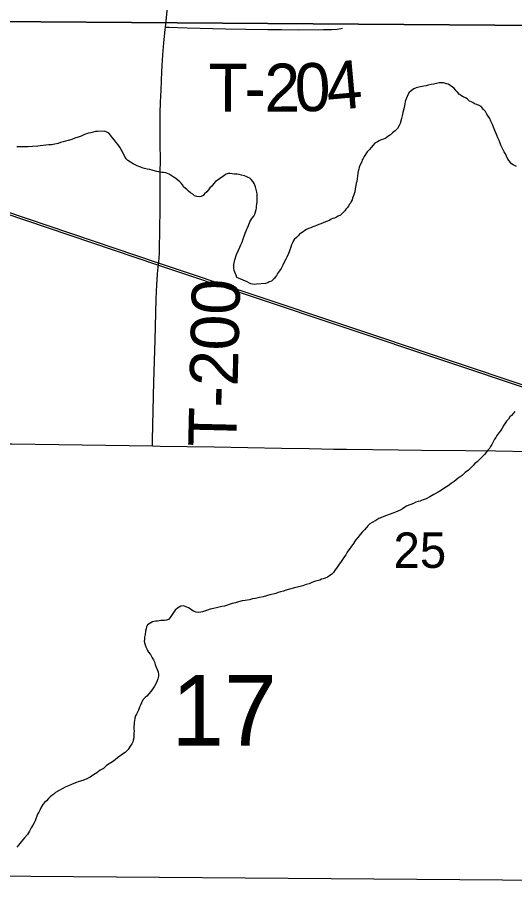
# Model space of a CAD drawing. Extents: x 2.4 to 73.1, y 4.5 to 25.6.
# Drawn here: x 33.042 to 33.336, y 22.115 to 22.627 of the extents above; entities that cross this region are included whole.
import ezdxf

# ---------------------------------------------------------------- set-up
doc = ezdxf.new("R2010")
doc.units = 0
for name, color, linetype in [('GM_X_County_Road', 7, 'Continuous'), ('GM_X_Minor_River', 7, 'Continuous'), ('GM_X_Rail_Line', 7, 'Continuous'), ('GM_X_Section', 7, 'Continuous'), ('GM_X_Section_Text', 7, 'Continuous'), ('GM_X_Township_Road', 7, 'Continuous'), ('GM_X_Township_Road_Text', 7, 'Continuous')]:
    doc.layers.add(name, color=color, linetype=linetype)

msp = doc.modelspace()

# ---------------------------------------------------------------- linework, layer by layer
at = {"layer": 'GM_X_County_Road'}
for points in [[(33.02645, 22.37476), (33.03888, 22.37466), (33.1082, 22.37368), (33.12199, 22.37343)], [(33.12199, 22.37343), (33.12654, 22.37335), (33.15855, 22.37294), (33.19834, 22.37219), (33.2145, 22.37194), (33.2291, 22.37161), (33.23656, 22.37157), (33.26734, 22.37111), (33.28101, 22.37095), (33.30712, 22.37067), (33.32484, 22.37046), (33.34473, 22.3702), (33.35934, 22.36986), (33.37363, 22.3697), (33.38233, 22.36961), (33.39788, 22.36951), (33.43642, 22.36906), (33.46004, 22.36895), (33.47186, 22.36883), (33.49797, 22.36822), (33.51599, 22.36802), (33.51997, 22.36798), (33.53391, 22.3678)]]:
    msp.add_lwpolyline(points, dxfattribs=at)
at = {"layer": 'GM_X_Minor_River'}
for points in [[(33.3371, 22.53863), (33.33522, 22.53963), (33.3341, 22.54023), (33.33281, 22.54197), (33.33207, 22.54294), (33.33117, 22.54467), (33.33063, 22.54601), (33.3299, 22.54717), (33.329, 22.5489), (33.32845, 22.55006), (33.32791, 22.55121), (33.32737, 22.55236), (33.32684, 22.5539), (33.32612, 22.55562), (33.3254, 22.55716), (33.32487, 22.5585), (33.32433, 22.55985), (33.32362, 22.56176), (33.3229, 22.56349), (33.322, 22.56541), (33.32128, 22.56695), (33.32036, 22.5683), (33.31963, 22.56946), (33.31872, 22.571), (33.31762, 22.57236), (33.31633, 22.5741), (33.31502, 22.5747), (33.3137, 22.57531), (33.31238, 22.57572), (33.31126, 22.57632), (33.30938, 22.57713), (33.30789, 22.57849), (33.30696, 22.57909), (33.30564, 22.57969), (33.30452, 22.58029), (33.3034, 22.58108), (33.30229, 22.58243), (33.30118, 22.5836), (33.30027, 22.58495), (33.29877, 22.58594), (33.29765, 22.58673), (33.29672, 22.58732), (33.29577, 22.58754), (33.29407, 22.58796), (33.29275, 22.58799), (33.29142, 22.58803), (33.28989, 22.58768), (33.28836, 22.58734), (33.28664, 22.58701), (33.28493, 22.58667), (33.28378, 22.58632), (33.28244, 22.58598), (33.2813, 22.58581), (33.28034, 22.58565), (33.27939, 22.58548), (33.27786, 22.58514), (33.27651, 22.58442), (33.27478, 22.58332), (33.27341, 22.58203), (33.27241, 22.57996), (33.272, 22.57865), (33.27139, 22.57695), (33.27116, 22.57544), (33.27073, 22.57355), (33.2699, 22.57053), (33.26946, 22.56845), (33.26924, 22.56694), (33.2684, 22.56392), (33.2678, 22.5628), (33.26681, 22.56111), (33.26545, 22.55963), (33.2639, 22.55853), (33.26273, 22.55723), (33.26099, 22.55632), (33.25983, 22.5554), (33.25848, 22.55468), (33.25715, 22.55433), (33.25599, 22.55379), (33.25503, 22.55325), (33.25349, 22.55234), (33.25213, 22.55104), (33.25134, 22.55011), (33.24997, 22.54844), (33.2488, 22.54733), (33.24702, 22.54452), (33.24643, 22.5434), (33.24583, 22.54247), (33.24562, 22.54133), (33.24461, 22.53927), (33.24421, 22.53814), (33.24399, 22.53701), (33.24358, 22.53588), (33.24335, 22.53436), (33.24313, 22.53304)], [(33.18342, 22.51499), (33.18365, 22.51651), (33.18386, 22.51745), (33.1839, 22.51897), (33.18394, 22.52068), (33.18379, 22.5222), (33.18363, 22.52334), (33.18295, 22.52659), (33.1824, 22.52755), (33.18205, 22.52851), (33.1815, 22.52947), (33.1804, 22.53083), (33.17947, 22.53162), (33.17853, 22.53202), (33.1774, 22.53262), (33.17646, 22.53302), (33.17457, 22.53345), (33.17325, 22.53386), (33.17193, 22.53409), (33.17041, 22.53412), (33.16908, 22.53416), (33.16776, 22.53438), (33.16662, 22.53441), (33.16509, 22.53388), (33.16392, 22.53296), (33.16238, 22.53186), (33.16083, 22.53076), (33.15928, 22.52966), (33.15811, 22.52836), (33.15713, 22.52705), (33.15596, 22.52594), (33.15517, 22.52482), (33.15419, 22.52352), (33.15283, 22.52241), (33.15186, 22.52149), (33.15071, 22.52095), (33.14956, 22.5206), (33.14824, 22.52082), (33.14692, 22.52124), (33.1458, 22.52221), (33.14449, 22.52301), (33.14338, 22.52398), (33.14245, 22.52477), (33.1404, 22.52653), (33.13986, 22.52749), (33.13894, 22.52865), (33.1382, 22.52962), (33.1369, 22.53061), (33.13578, 22.53158), (33.13428, 22.53257), (33.13298, 22.53336), (33.13185, 22.53396), (33.13091, 22.53436), (33.12997, 22.53477), (33.12846, 22.535), (33.12751, 22.53502), (33.12657, 22.53524), (33.12449, 22.53567), (33.12241, 22.53629), (33.12052, 22.53672), (33.11882, 22.53695), (33.11731, 22.53737), (33.11599, 22.53778), (33.11505, 22.53819), (33.11392, 22.53859), (33.11298, 22.539), (33.11186, 22.5396), (33.11054, 22.5402), (33.10905, 22.54119), (33.10737, 22.54218), (33.10644, 22.54315), (33.10589, 22.54411), (33.10517, 22.54546), (33.10408, 22.54758), (33.10354, 22.54873), (33.10262, 22.55008), (33.10171, 22.55144), (33.10079, 22.5526), (33.0995, 22.55415), (33.09839, 22.55551), (33.09729, 22.55706), (33.09618, 22.55822), (33.09468, 22.55902), (33.09355, 22.55943), (33.08956, 22.55934), (33.08842, 22.55918), (33.08689, 22.55884), (33.08555, 22.55849), (33.08422, 22.55834), (33.08287, 22.5578), (33.08134, 22.55727), (33.0798, 22.55655), (33.07808, 22.55583), (33.07616, 22.55531), (33.07444, 22.5546), (33.07214, 22.5539), (33.07061, 22.55355), (33.06927, 22.55321), (33.06774, 22.55268), (33.06621, 22.55215), (33.0643, 22.55181)], [(33.0643, 22.55181), (33.06239, 22.55148), (33.06068, 22.55134), (33.05897, 22.55119), (33.05744, 22.55104), (33.05573, 22.55089), (33.0542, 22.55055), (33.05116, 22.55044), (33.0485, 22.55013), (33.04603, 22.55019), (33.04394, 22.55024), (33.04185, 22.55029)], [(33.24313, 22.53304), (33.2429, 22.53134), (33.24267, 22.52982), (33.24245, 22.52869), (33.24223, 22.52737), (33.2418, 22.52548), (33.24156, 22.52358), (33.24095, 22.52189), (33.24055, 22.52095), (33.24014, 22.51982), (33.23993, 22.51888), (33.23933, 22.51794), (33.23893, 22.517), (33.23833, 22.51607), (33.23774, 22.51514), (33.23696, 22.51421), (33.23618, 22.51328), (33.23558, 22.51234), (33.23305, 22.50975), (33.23171, 22.50921), (33.23074, 22.50867), (33.22959, 22.50813), (33.22863, 22.50777), (33.22767, 22.50741), (33.22671, 22.50687), (33.22537, 22.50633), (33.22421, 22.50579), (33.22287, 22.50526), (33.22153, 22.50472), (33.22038, 22.50437), (33.21884, 22.50365), (33.21788, 22.50329), (33.21673, 22.50294), (33.21558, 22.5024), (33.21424, 22.50187), (33.21309, 22.50133), (33.21212, 22.50078), (33.21097, 22.50005), (33.21, 22.49932), (33.20884, 22.49859), (33.20806, 22.49766), (33.20708, 22.49654), (33.20572, 22.49544), (33.20513, 22.4945), (33.20473, 22.49356), (33.20412, 22.49225), (33.20371, 22.49093), (33.2031, 22.48943), (33.20269, 22.48811), (33.20229, 22.48717), (33.20148, 22.4851), (33.20087, 22.48379), (33.19988, 22.4821), (33.19907, 22.48022), (33.19808, 22.47835), (33.19709, 22.47686), (33.19591, 22.47537), (33.19532, 22.47424), (33.19472, 22.47331), (33.19394, 22.47238), (33.19238, 22.4709), (33.19104, 22.47036), (33.19008, 22.46982), (33.18874, 22.46947), (33.18341, 22.46904), (33.18208, 22.46888), (33.18113, 22.46909), (33.18019, 22.46931), (33.17925, 22.46971), (33.17794, 22.4705), (33.17568, 22.47132), (33.17417, 22.47193), (33.17286, 22.47253), (33.17192, 22.47294), (33.17139, 22.47428), (33.17103, 22.47524), (33.17067, 22.4762), (33.17032, 22.47715), (33.16998, 22.47868), (33.17003, 22.48077), (33.17066, 22.48341), (33.17169, 22.48661), (33.1729, 22.48924), (33.1737, 22.49093), (33.1743, 22.49225), (33.17491, 22.49394), (33.17553, 22.49582), (33.17614, 22.49733), (33.17676, 22.49921), (33.17736, 22.50052), (33.17776, 22.50146), (33.17817, 22.5024), (33.17877, 22.50372), (33.17958, 22.50579), (33.18077, 22.50784), (33.18195, 22.50933), (33.18255, 22.51046), (33.18296, 22.51178), (33.18318, 22.5131), (33.18339, 22.51404), (33.18342, 22.51499)], [(33.33613, 22.39376), (33.33516, 22.39265), (33.33418, 22.39153), (33.3332, 22.39061), (33.33241, 22.3893), (33.33124, 22.388), (33.33045, 22.38688), (33.32966, 22.38576), (33.32867, 22.38388), (33.32768, 22.38239), (33.3267, 22.38127), (33.32552, 22.3796), (33.32492, 22.37847), (33.32414, 22.37735), (33.32334, 22.37585), (33.32254, 22.37435), (33.32175, 22.37305), (33.32115, 22.37192), (33.32018, 22.371), (33.31959, 22.37006), (33.31821, 22.36839), (33.31393, 22.36413), (33.31257, 22.36302), (33.3114, 22.36172), (33.31004, 22.36043), (33.30868, 22.35913), (33.30674, 22.35766), (33.30499, 22.356), (33.30267, 22.35435), (33.30034, 22.35251)], [(33.30034, 22.35251), (33.29841, 22.35123), (33.29667, 22.34994), (33.29474, 22.34866), (33.29281, 22.34738), (33.29088, 22.3461), (33.28818, 22.34465), (33.28587, 22.34338), (33.28375, 22.3421), (33.28145, 22.3414), (33.28011, 22.34087), (33.27896, 22.34052), (33.27762, 22.34017), (33.27628, 22.33944), (33.27474, 22.33891), (33.2734, 22.33838), (33.27206, 22.33784), (33.27109, 22.3373), (33.26974, 22.33619), (33.26839, 22.33547), (33.26705, 22.33493), (33.2657, 22.3344), (33.26455, 22.33385), (33.26187, 22.33297), (33.25976, 22.33208), (33.25727, 22.33119), (33.25573, 22.33047), (33.25399, 22.32938), (33.25188, 22.32829), (33.25052, 22.32737), (33.24955, 22.32645), (33.24838, 22.32515), (33.24721, 22.32385), (33.24584, 22.32255), (33.24467, 22.32106), (33.2433, 22.31939), (33.24192, 22.31772), (33.24074, 22.31585), (33.237, 22.31063), (33.2362, 22.30913), (33.23542, 22.30801), (33.23463, 22.30689), (33.23384, 22.30577), (33.23305, 22.30465), (33.23226, 22.30353), (33.23148, 22.30241), (33.23069, 22.30129), (33.2299, 22.30017), (33.22891, 22.29868), (33.22794, 22.29775), (33.22658, 22.29665), (33.22543, 22.29591), (33.22408, 22.29538), (33.22293, 22.29484), (33.22198, 22.29467), (33.22082, 22.29413), (33.2193, 22.29379), (33.21834, 22.29344), (33.21719, 22.29308), (33.21585, 22.29255), (33.2145, 22.29201), (33.21278, 22.29149), (33.21086, 22.29078), (33.20857, 22.29027), (33.20589, 22.28957), (33.20303, 22.28889), (33.20092, 22.28818), (33.19939, 22.28765), (33.19767, 22.28731), (33.19633, 22.28678), (33.19499, 22.28624), (33.19327, 22.2859), (33.19135, 22.28538), (33.18944, 22.28486), (33.18734, 22.28435), (33.18524, 22.28383), (33.18295, 22.28332), (33.18104, 22.28299), (33.17932, 22.28246), (33.17684, 22.28214), (33.17493, 22.28181), (33.17283, 22.28129), (33.17111, 22.28077), (33.16919, 22.28025), (33.1646, 22.27884), (33.16307, 22.2785), (33.16136, 22.27817), (33.15983, 22.27783), (33.1581, 22.2773), (33.15601, 22.27697), (33.15448, 22.27644), (33.15275, 22.27573), (33.1516, 22.27538), (33.15065, 22.27521), (33.14912, 22.27506), (33.1478, 22.27528), (33.14629, 22.27589), (33.14535, 22.27629), (33.14423, 22.27708), (33.1433, 22.27767), (33.14236, 22.27808)], [(33.14236, 22.27808), (33.14048, 22.27889), (33.13877, 22.27874), (33.13781, 22.27819), (33.13684, 22.27765), (33.13548, 22.27635), (33.1345, 22.27505), (33.13371, 22.27374), (33.13252, 22.27206), (33.13155, 22.27095), (33.1302, 22.27041), (33.12906, 22.27025), (33.12792, 22.27028), (33.12697, 22.2703), (33.12602, 22.27014), (33.12506, 22.26997), (33.12392, 22.26981), (33.12297, 22.26964), (33.12201, 22.26948), (33.12009, 22.26839), (33.11912, 22.26765), (33.11852, 22.26653), (33.1183, 22.26539), (33.11789, 22.26388), (33.11765, 22.26199), (33.11723, 22.26048), (33.11719, 22.25897), (33.11717, 22.25802), (33.11733, 22.25706), (33.11769, 22.25591), (33.11804, 22.25477), (33.11858, 22.25361), (33.11912, 22.25246), (33.11966, 22.2515), (33.12077, 22.25014), (33.12186, 22.24821), (33.12259, 22.24705), (33.12313, 22.2459), (33.12367, 22.24437), (33.12419, 22.24265), (33.12491, 22.24092), (33.12545, 22.23976), (33.12561, 22.23862), (33.12558, 22.23729), (33.12516, 22.23578), (33.12475, 22.23465), (33.12415, 22.23334), (33.12315, 22.23147), (33.12197, 22.2296), (33.12098, 22.22829), (33.11981, 22.22699), (33.11864, 22.2255), (33.11767, 22.22477), (33.11631, 22.22347), (33.1149, 22.22028), (33.11429, 22.21897), (33.11368, 22.21727), (33.11308, 22.21615), (33.11249, 22.21502), (33.11189, 22.2139), (33.11166, 22.21258), (33.11144, 22.21106), (33.11122, 22.21012), (33.11119, 22.20898), (33.11097, 22.20766), (33.11094, 22.20652), (33.11109, 22.20481), (33.11106, 22.20348), (33.11103, 22.20234), (33.111, 22.20101), (33.11058, 22.1995), (33.11037, 22.19856), (33.10977, 22.19743), (33.10878, 22.19594), (33.10759, 22.19407), (33.10584, 22.19221), (33.10487, 22.19167), (33.10352, 22.19075), (33.10139, 22.1891), (33.10003, 22.18799), (33.09829, 22.18671), (33.09637, 22.18562), (33.09482, 22.18452), (33.09307, 22.18285), (33.09114, 22.18176), (33.08921, 22.18029), (33.08708, 22.17902), (33.08515, 22.17774), (33.08323, 22.17664), (33.08093, 22.17575), (33.07863, 22.17505), (33.07652, 22.17434), (33.07422, 22.17345), (33.0723, 22.17255), (33.07038, 22.17184), (33.06479, 22.16856), (33.06363, 22.16764), (33.06247, 22.16691), (33.0615, 22.16599), (33.06053, 22.16506), (33.05935, 22.16376)], [(33.05935, 22.16376), (33.05819, 22.16265), (33.05721, 22.16154), (33.05622, 22.16005), (33.05562, 22.15854), (33.05482, 22.15704), (33.05403, 22.15573), (33.05362, 22.1546), (33.05301, 22.1531), (33.0526, 22.15197), (33.052, 22.15066), (33.05121, 22.14935), (33.05041, 22.14766), (33.04941, 22.14578), (33.04822, 22.14373), (33.04646, 22.14187), (33.04548, 22.14057), (33.04431, 22.13946), (33.04275, 22.1376), (33.04176, 22.13629)]]:
    msp.add_lwpolyline(points, dxfattribs=at)
at = {"layer": 'GM_X_Rail_Line'}
for points in [[(32.73645, 22.61193), (33.12493, 22.48054), (33.46002, 22.36848), (33.53437, 22.34358), (33.5691, 22.33375), (33.59988, 22.32785), (33.62445, 22.32326), (33.65262, 22.31965), (33.6821, 22.31769), (34.03881, 22.31179), (34.37193, 22.30622), (34.42761, 22.30589), (34.46888, 22.30458), (34.50754, 22.3072), (34.56158, 22.31015), (34.62578, 22.31539), (34.67295, 22.31965), (34.92476, 22.34017)], [(32.73685, 22.61311), (33.12533, 22.48172), (33.46041, 22.36966), (33.53474, 22.34476), (33.56938, 22.33496), (33.60012, 22.32907), (33.62465, 22.32449), (33.65274, 22.32089), (33.68215, 22.31893), (34.03883, 22.31303), (34.37194, 22.30746), (34.42764, 22.30713), (34.46886, 22.30582), (34.50746, 22.30844), (34.5615, 22.31139), (34.62568, 22.31663), (34.67285, 22.32089), (34.92723, 22.34151)]]:
    msp.add_lwpolyline(points, dxfattribs=at)
at = {"layer": 'GM_X_Section'}
for points in [[(33.54562, 23.11902), (33.5389, 22.62058), (33.02904, 22.62432), (33.03536, 23.12164)], [(33.5389, 22.62058), (33.53887, 22.61906), (33.53166, 22.11533), (33.02446, 22.1192), (33.02904, 22.62432)]]:
    msp.add_lwpolyline(points, close=True, dxfattribs=at)
at = {"layer": 'GM_X_Township_Road'}
for points in [[(33.12965, 22.62102), (33.13029, 22.6265), (33.13135, 22.63671), (33.133, 22.65217), (33.13505, 22.67071), (33.13653, 22.68368), (33.13807, 22.69727), (33.13927, 22.70872), (33.1394, 22.71012), (33.1395, 22.71133)], [(33.12199, 22.37343), (33.12207, 22.37708), (33.12273, 22.41139), (33.12354, 22.43594), (33.12427, 22.46019), (33.12466, 22.46888), (33.12479, 22.47136), (33.12501, 22.47509), (33.12533, 22.47911), (33.12568, 22.48219), (33.12591, 22.48466), (33.12606, 22.48745), (33.12619, 22.49117), (33.12638, 22.49987), (33.1265, 22.51511), (33.12664, 22.53438), (33.12665, 22.54308), (33.12658, 22.55148), (33.12651, 22.56173), (33.12658, 22.57012), (33.12679, 22.57664), (33.12716, 22.58378), (33.12761, 22.59465), (33.12817, 22.60458), (33.12869, 22.61171), (33.12947, 22.61943), (33.12965, 22.62102)], [(33.12965, 22.62102), (33.13167, 22.62094), (33.137, 22.62075), (33.14259, 22.62056), (33.16528, 22.61995), (33.17709, 22.61969), (33.19015, 22.61953), (33.19823, 22.61947), (33.20818, 22.61945), (33.2231, 22.61946), (33.22776, 22.61951), (33.23117, 22.61975), (33.23332, 22.62007), (33.23423, 22.62028)]]:
    msp.add_lwpolyline(points, dxfattribs=at)

# ---------------------------------------------------------------- texts
at = {"layer": 'GM_X_Section_Text'}
for s, height, p in [('25', 0.020928, (33.26444, 22.30136)), ('17', 0.041856, (33.13319, 22.19629))]:
    msp.add_text(s, height=height, rotation=0, dxfattribs=at).set_placement(p)
at = {"layer": 'GM_X_Township_Road_Text'}
for s, height, rotation, p in [('4', 0.02841, 5.1863, (33.22587, 22.57162)), ('T', 0.02841, 359.7686, (33.15504, 22.57104)), ('2', 0.02841, 0.2524, (33.18821, 22.57092)), ('0', 0.02841, 1.6221, (33.20645, 22.57101)), ('-', 0.02841, 359.8392, (33.17632, 22.57095)), ('T-200', 0.028409, 88.6241, (33.17145, 22.37261))]:
    msp.add_text(s, height=height, rotation=rotation, dxfattribs=at).set_placement(p)

doc.saveas('drawing.dxf')
